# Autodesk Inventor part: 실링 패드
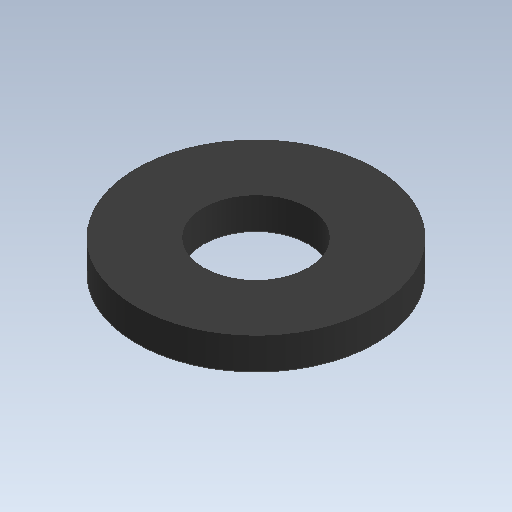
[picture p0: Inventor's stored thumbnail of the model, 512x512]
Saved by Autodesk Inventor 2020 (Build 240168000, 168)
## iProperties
Created: 2024-09
Part Number: 실링 패드
Material: 고무
Document SubType Name: Modeling
Designer: oem
Density: 0.93 g/cm^3
Appearance: 기본값
Author: jhkim
Sending System: Autodesk Inventor 2025
Preprocessor: ST-DEVELOPER v20
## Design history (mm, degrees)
feature "솔리드1"
node "솔리드2"
